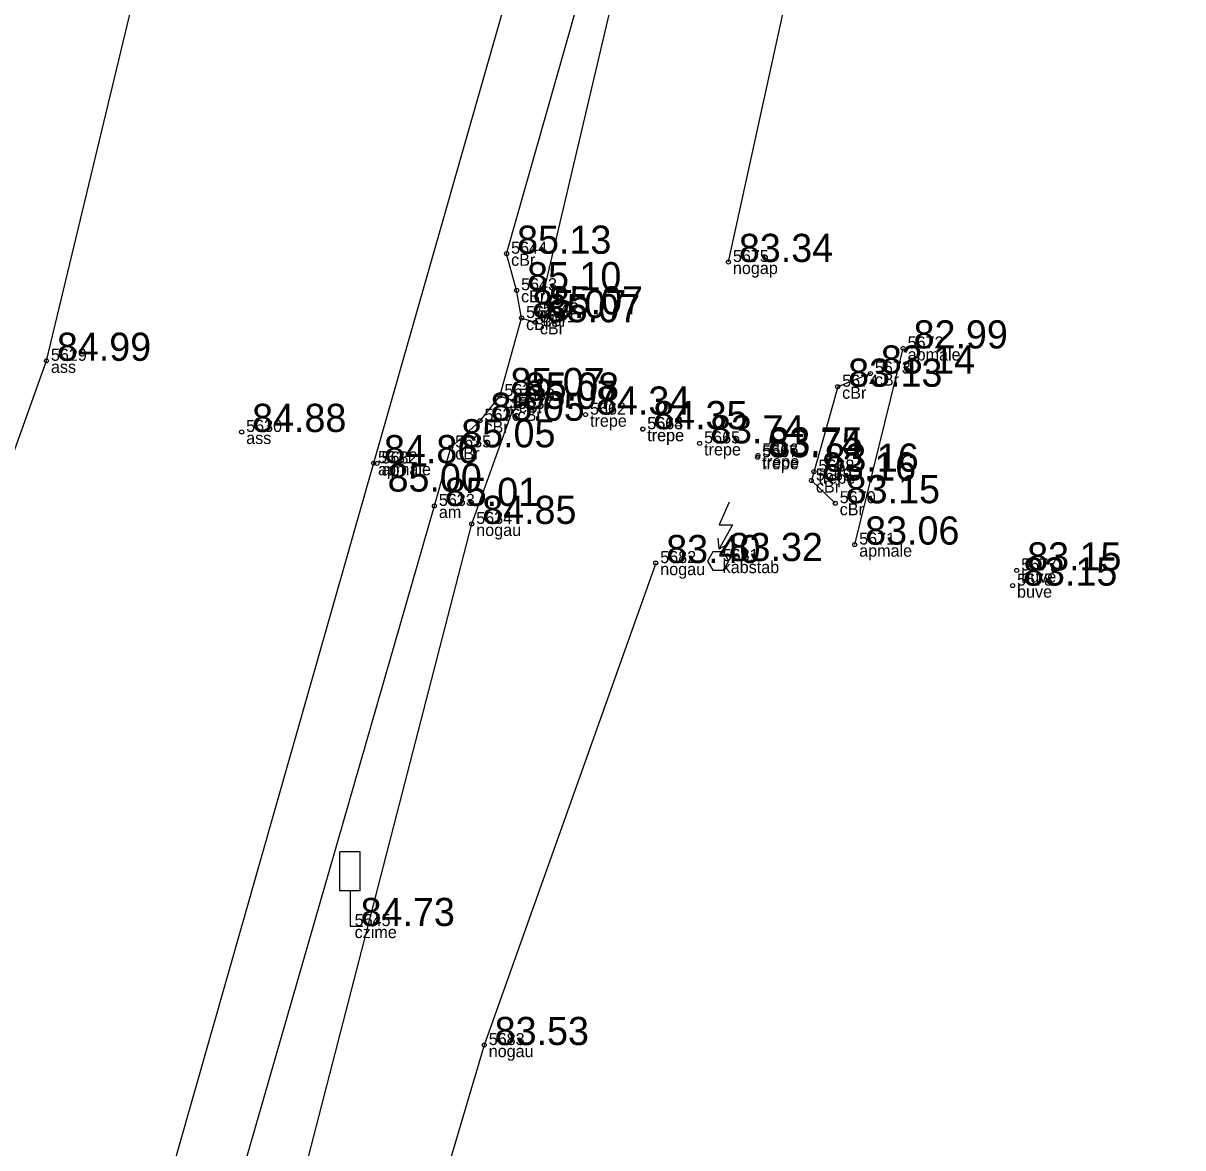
# Model space of a CAD drawing. Extents: x 614911 to 615803, y 262110 to 264311.
# Drawn here: x 615563.8 to 615592.62, y 262791.37 to 262819.32 of the extents above; entities that cross this region are included whole.
import ezdxf

# ---------------------------------------------------------------- set-up
doc = ezdxf.new("R2010")
doc.units = 0
for name, color, linetype in [('Level 12', 7, 'Continuous'), ('Level 16', 7, 'Continuous'), ('Level 31', 7, 'Continuous'), ('Level 37', 7, 'Continuous'), ('Level 53', 7, 'Continuous'), ('Level 54', 7, 'Continuous'), ('Level 57', 7, 'Continuous'), ('Level 58', 7, 'Continuous')]:
    doc.layers.add(name, color=color, linetype=linetype)

msp = doc.modelspace()

# ---------------------------------------------------------------- linework, layer by layer
at = {"layer": 'Level 12'}
msp.add_line((615581.098, 262806.252), (615581.339, 262806.391), dxfattribs=at)
msp.add_lwpolyline([(615581.347, 262807.414), (615581.098, 262806.851), (615581.434, 262806.851), (615581.098, 262806.252), (615581.076, 262806.522)], dxfattribs=at)
msp.add_lwpolyline([(615580.942, 262805.722), (615581.208, 262805.722), (615581.341, 262805.952), (615581.208, 262806.183), (615580.942, 262806.183), (615580.809, 262805.952)], close=True, dxfattribs=at)
at = {"layer": 'Level 16'}
for p, q in [((615572.175, 262798.728), (615571.675, 262798.728)), ((615571.675, 262797.759), (615571.675, 262798.728)), ((615572.175, 262797.759), (615572.175, 262798.728)), ((615572.175, 262797.759), (615571.675, 262797.759)), ((615571.929, 262797.759), (615571.929, 262796.881)), ((615571.929, 262796.881), (615572.244, 262796.881))]:
    msp.add_line(p, q, dxfattribs=at)
at = {"layer": 'Level 31'}
for points in [[(615632.734, 262974.874), (615627.762, 262975.783), (615624.583, 262974.081), (615622.329, 262970.726), (615619.288, 262963.641), (615611.976, 262941.852), (615605.37, 262920.098), (615598.524, 262898.844), (615592.115, 262877.692), (615586.071, 262858.355), (615583.42, 262849.533), (615582.048, 262845.554), (615581.571, 262838.931), (615579.909, 262826.022), (615579.783, 262825.588), (615576.605, 262812.081)], [(615581.33, 262813.385), (615587.235, 262840.341), (615585.874, 262843.893), (615588.538, 262850.225), (615593.068, 262864.597), (615600.932, 262884.287), (615612.047, 262917.578), (615615.98, 262929.024), (615621.827, 262931.099), (615623.831, 262935.169), (615622.903, 262940.536), (615628.682, 262961.888), (615634.511, 262966.199), (615634.511, 262966.199)], [(615567.19, 262773.86), (615567.235, 262778.049), (615570.024, 262787.772), (615574.951, 262806.875), (615575.977, 262809.733)], [(615579.524, 262805.902), (615575.261, 262793.923), (615571.876, 262782.514), (615570.677, 262777.527), (615567.19, 262773.86)]]:
    msp.add_lwpolyline(points, dxfattribs=at)
at = {"layer": 'Level 37'}
msp.add_line((615584.468, 262806.361), (615585.672, 262811.236), dxfattribs=at)
for points in [[(615552.83, 262775.419), (615557.688, 262792.217), (615564.381, 262810.929), (615568.874, 262829.598), (615578.474, 262860.105), (615584.765, 262880.506), (615591.133, 262901.009), (615597.793, 262922.52), (615604.506, 262944.221), (615611.821, 262967.016), (615619.311, 262990.31), (615624.144, 263005.661), (615628.856, 263023.992)], [(615633.153, 262995.478), (615630.105, 262994.778), (615627.249, 262993.097), (615624.165, 262989.775), (615623.012, 262986.721), (615615.941, 262964.659), (615608.941, 262942.572), (615602.23, 262921.018), (615595.493, 262899.514), (615589.041, 262878.574), (615583.023, 262859.136), (615579.804, 262848.845), (615577.579, 262826.156), (615572.51, 262808.384), (615566.84, 262788.492), (615562.353, 262772.755), (615562.228, 262772.268), (615562.322, 262770.686), (615563.546, 262768.507), (615565.703, 262767.319), (615569.868, 262766.432), (615584.992, 262762.796)], [(615576.19, 262811.993), (615576.066, 262812.682), (615575.818, 262813.59), (615579.291, 262825.832), (615581.523, 262848.494), (615584.551, 262858.603), (615590.575, 262878.181), (615597.215, 262899.18), (615604.023, 262920.582), (615610.418, 262942.235), (615617.538, 262964.274), (615623.159, 262980.563)], [(615575.652, 262810.052), (615576.19, 262811.993), (615576.532, 262811.887)], [(615584.858, 262810.612), (615584.046, 262810.285), (615583.392, 262807.954), (615583.985, 262807.389)], [(615575.157, 262809.439), (615575.652, 262810.052), (615576.009, 262809.939)], [(615576.777, 262775.478), (615569.363, 262768.926), (615567.812, 262768.576), (615565.869, 262769.072), (615564.804, 262769.703), (615564.095, 262770.764), (615563.953, 262772.067), (615568.503, 262788.143), (615574.022, 262807.322), (615574.429, 262808.778), (615575.157, 262809.439)]]:
    msp.add_lwpolyline(points, dxfattribs=at)
at = {"layer": 'Level 57'}
for centre in [(615575.818, 262813.59), (615581.33, 262813.385), (615576.066, 262812.682), (615576.19, 262811.993), (615576.532, 262811.887), (615576.605, 262812.081), (615585.672, 262811.236), (615564.381, 262810.929), (615584.858, 262810.612), (615584.046, 262810.285), (615575.652, 262810.052), (615576.009, 262809.939), (615575.977, 262809.733), (615577.779, 262809.591), (615575.157, 262809.439), (615579.2, 262809.23), (615579.204, 262809.23), (615569.233, 262809.161), (615574.429, 262808.778), (615580.615, 262808.877), (615572.51, 262808.384), (615572.599, 262808.378), (615582.054, 262808.532), (615582.064, 262808.577), (615583.456, 262808.174), (615583.392, 262807.954), (615574.022, 262807.322), (615583.985, 262807.389), (615574.951, 262806.875), (615584.468, 262806.361), (615579.524, 262805.902), (615588.495, 262805.719), (615588.392, 262805.342), (615575.261, 262793.923)]:
    msp.add_circle(centre, 0.05, dxfattribs=at)
at = {"layer": 'Level 58'}
for centre in [(615575.818, 262813.59), (615581.33, 262813.385), (615576.066, 262812.682), (615576.19, 262811.993), (615576.532, 262811.887), (615576.605, 262812.081), (615585.672, 262811.236), (615564.381, 262810.929), (615584.858, 262810.612), (615584.046, 262810.285), (615575.652, 262810.052), (615576.009, 262809.939), (615575.977, 262809.733), (615577.779, 262809.591), (615575.157, 262809.439), (615579.2, 262809.23), (615579.204, 262809.23), (615569.233, 262809.161), (615574.429, 262808.778), (615580.615, 262808.877), (615572.51, 262808.384), (615572.599, 262808.378), (615582.054, 262808.532), (615582.064, 262808.577), (615583.456, 262808.174), (615583.392, 262807.954), (615574.022, 262807.322), (615583.985, 262807.389), (615574.951, 262806.875), (615584.468, 262806.361), (615579.524, 262805.902), (615588.495, 262805.719), (615588.392, 262805.342), (615575.261, 262793.923)]:
    msp.add_circle(centre, 0.05, dxfattribs=at)

# ---------------------------------------------------------------- texts
at = {"layer": 'Level 53'}
for s, p in [(' cBr', (615575.818, 262813.29)), (' nogap', (615581.33, 262813.085)), (' cBr', (615576.066, 262812.382)), (' cBr', (615576.19, 262811.693)), (' cBr', (615576.532, 262811.587)), (' cBr', (615576.605, 262811.781)), (' apmale', (615585.672, 262810.936)), (' ass', (615564.381, 262810.629)), (' cBr', (615584.858, 262810.312)), (' cBr', (615584.046, 262809.985)), (' cBr', (615575.652, 262809.752)), (' cBr', (615576.009, 262809.639)), (' cBr', (615575.977, 262809.433)), (' trepe', (615577.779, 262809.291)), (' cBr', (615575.157, 262809.139)), (' ass', (615569.233, 262808.861)), (' trepe', (615579.2, 262808.93)), (' trepe', (615579.204, 262808.93)), (' cBr', (615574.429, 262808.478)), (' trepe', (615580.615, 262808.577)), (' trepe', (615582.054, 262808.232)), (' trepe', (615582.064, 262808.277)), (' apmale', (615572.51, 262808.084)), (' ap', (615572.599, 262808.078)), (' trepe', (615583.456, 262807.874)), (' cBr', (615583.392, 262807.654)), (' cBr', (615583.985, 262807.089)), (' am', (615574.022, 262807.022)), (' nogau', (615574.951, 262806.575)), (' apmale', (615584.468, 262806.061)), (' nogau', (615579.524, 262805.602)), (' kabstab', (615581.075, 262805.652)), (' buve', (615588.495, 262805.419)), (' buve', (615588.392, 262805.042)), (' czime', (615571.929, 262796.581)), (' nogau', (615575.261, 262793.623))]:
    msp.add_text(s, height=0.3, dxfattribs=at).set_placement(p)
at = {"layer": 'Level 54'}
for s, p in [(' 5644', (615575.818, 262813.59)), (' 5675', (615581.33, 262813.385)), (' 5643', (615576.066, 262812.682)), (' 5640', (615576.19, 262811.993)), (' 5641', (615576.532, 262811.887)), (' 5642', (615576.605, 262812.081)), (' 5672', (615585.672, 262811.236)), (' 5629', (615564.381, 262810.929)), (' 5673', (615584.858, 262810.612)), (' 5674', (615584.046, 262810.285)), (' 5639', (615575.652, 262810.052)), (' 5638', (615576.009, 262809.939)), (' 5637', (615575.977, 262809.733)), (' 5662', (615577.779, 262809.591)), (' 5636', (615575.157, 262809.439)), (' 5630', (615569.233, 262809.161)), (' 5663', (615579.2, 262809.23)), (' 5664', (615579.204, 262809.23)), (' 5635', (615574.429, 262808.778)), (' 5665', (615580.615, 262808.877)), (' 5667', (615582.054, 262808.532)), (' 5666', (615582.064, 262808.577)), (' 5631', (615572.51, 262808.384)), (' 5632', (615572.599, 262808.378)), (' 5668', (615583.456, 262808.174)), (' 5669', (615583.392, 262807.954)), (' 5633', (615574.022, 262807.322)), (' 5670', (615583.985, 262807.389)), (' 5634', (615574.951, 262806.875)), (' 5671', (615584.468, 262806.361)), (' 5682', (615579.524, 262805.902)), (' 5681', (615581.075, 262805.952)), (' 5677', (615588.495, 262805.719)), (' 5678', (615588.392, 262805.342)), (' 5645', (615571.929, 262796.881)), (' 5683', (615575.261, 262793.923))]:
    msp.add_text(s, height=0.3, dxfattribs=at).set_placement(p)
at = {"layer": 'Level 58'}
for s, p in [(' 85.13', (615575.818, 262813.59)), (' 83.34', (615581.33, 262813.385)), (' 85.10', (615576.066, 262812.682)), (' 85.07', (615576.605, 262812.081)), (' 85.07', (615576.19, 262811.993)), (' 85.07', (615576.532, 262811.887)), (' 82.99', (615585.672, 262811.236)), (' 84.99', (615564.381, 262810.929)), (' 83.14', (615584.858, 262810.612)), (' 85.07', (615575.652, 262810.052)), (' 83.13', (615584.046, 262810.285)), (' 85.07', (615575.977, 262809.733)), (' 85.08', (615576.009, 262809.939)), (' 85.05', (615575.157, 262809.439)), (' 84.34', (615577.779, 262809.591)), (' 84.88', (615569.233, 262809.161)), (' 84.35', (615579.2, 262809.23)), (' 84.35', (615579.204, 262809.23)), (' 83.74', (615580.615, 262808.877)), (' 85.05', (615574.429, 262808.778)), (' 83.75', (615582.064, 262808.577)), (' 84.86', (615572.51, 262808.384)), (' 83.74', (615582.054, 262808.532)), (' 83.16', (615583.456, 262808.174)), (' 83.16', (615583.392, 262807.954)), (' 85.00', (615572.599, 262807.678)), (' 85.01', (615574.022, 262807.322)), (' 83.15', (615583.985, 262807.389)), (' 84.85', (615574.951, 262806.875)), (' 83.06', (615584.468, 262806.361)), (' 83.40', (615579.524, 262805.902)), (' 83.32', (615581.075, 262805.952)), (' 83.15', (615588.495, 262805.719)), (' 83.15', (615588.392, 262805.342)), (' 84.73', (615571.929, 262796.881)), (' 83.53', (615575.261, 262793.923))]:
    msp.add_text(s, height=0.7, dxfattribs=at).set_placement(p)

doc.saveas('drawing.dxf')
